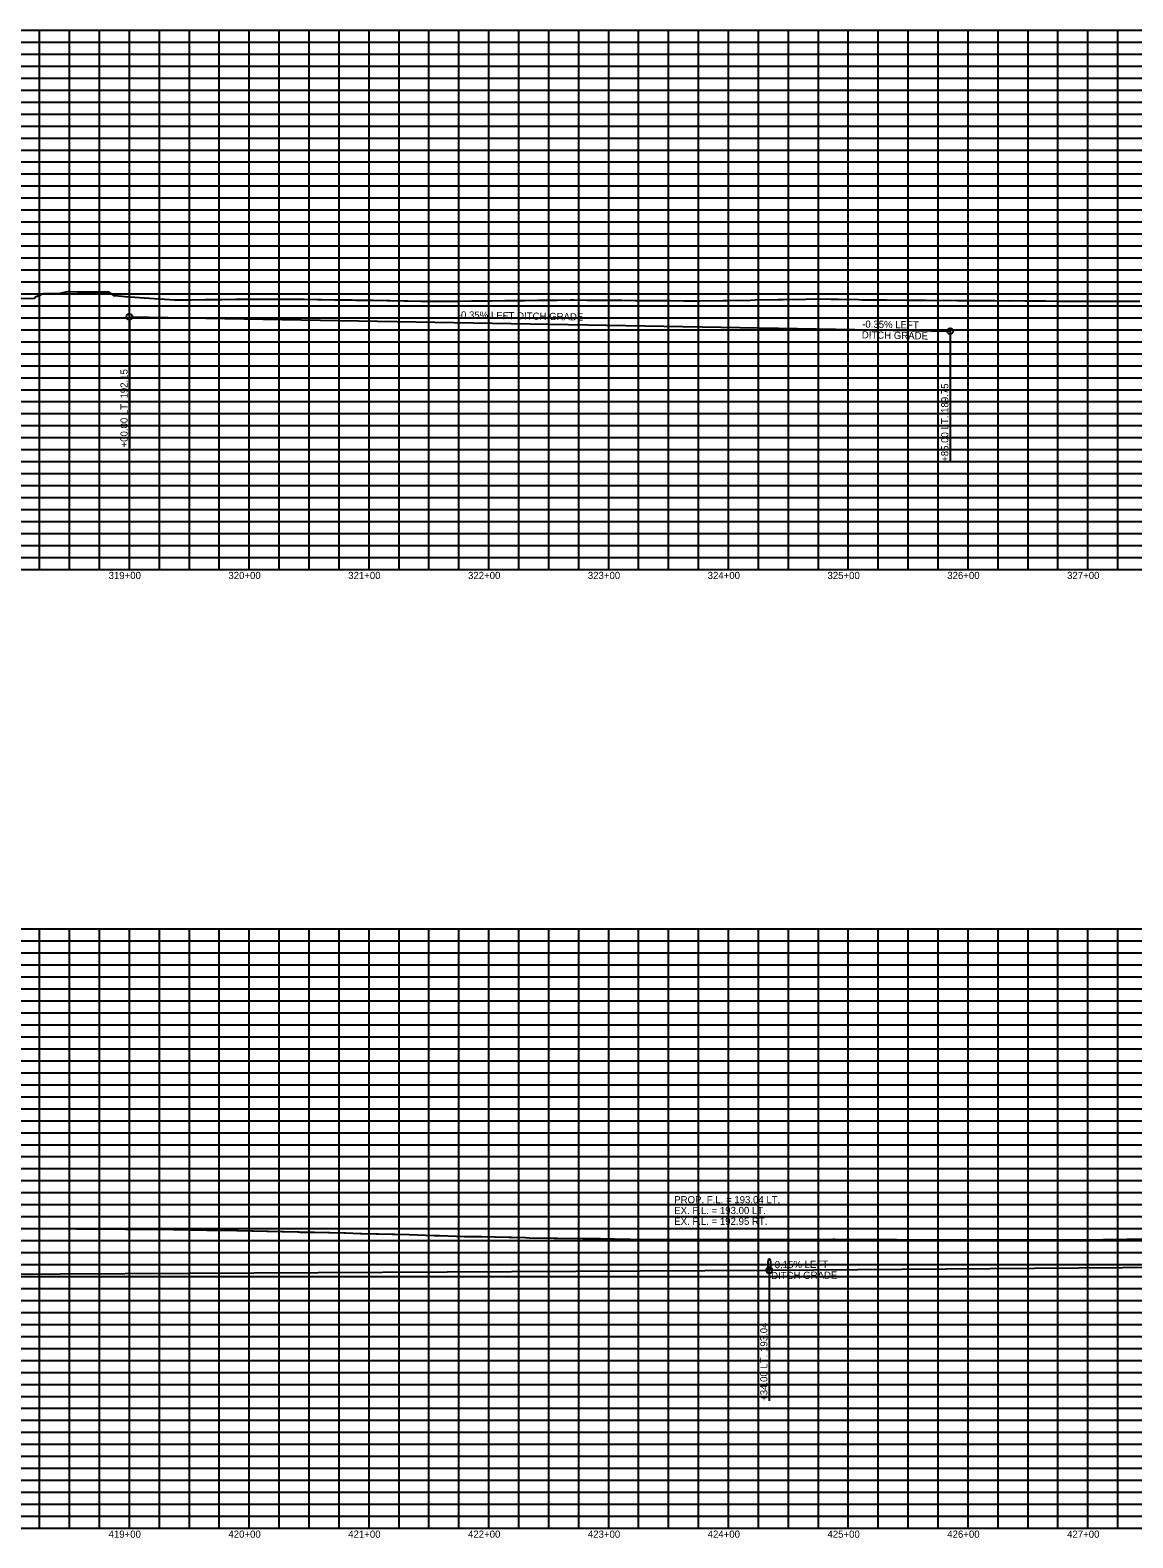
# Model space of a CAD drawing. Extents: x 1399671 to 1408349, y 1930471 to 1933387.
# Drawn here: x 1402141 to 1403062, y 1930471 to 1931729 of the extents above; entities that cross this region are included whole.
import ezdxf

# ---------------------------------------------------------------- set-up
doc = ezdxf.new("R2010")
doc.units = 0
for name, color, linetype in [('R_Drainage', 7, 'Continuous'), ('R_Exist Surface', 7, 'Continuous'), ('R_Grid', 7, 'Continuous'), ('R_Grid Annot', 7, 'Continuous'), ('R_Vert Alg', 7, 'Continuous'), ('R_Vert Alg Annot', 7, 'Continuous')]:
    doc.layers.add(name, color=color, linetype=linetype)

msp = doc.modelspace()

# ---------------------------------------------------------------- linework, layer by layer
at = {"layer": 'R_Drainage'}
msp.add_ellipse((1402758.2, 1930698.6), major_axis=(0, 5), ratio=0.2, dxfattribs=at)
at = {"layer": 'R_Exist Surface'}
for points in [[(1402132, 1931504.6), (1402145.1, 1931504.9), (1402145.9, 1931506.1), (1402152.1, 1931508.8), (1402166.5, 1931509), (1402171.4, 1931510.3), (1402172.5, 1931510.4), (1402180.9, 1931510.2), (1402194, 1931510.3), (1402201.3, 1931510.2), (1402206.6, 1931510.3), (1402210.9, 1931507.1), (1402211.9, 1931507.1), (1402223.8, 1931506.2), (1402224.1, 1931506.2), (1402228.7, 1931505.8), (1402236.5, 1931505.3), (1402236.7, 1931505.2), (1402249, 1931504.4), (1402249.6, 1931504.4), (1402261.6, 1931503.5), (1402262.4, 1931503.5), (1402274.5, 1931503.7), (1402275.5, 1931503.6), (1402287.3, 1931503.8), (1402288.5, 1931503.8), (1402300.1, 1931503.9), (1402301.6, 1931503.9), (1402312.9, 1931504), (1402314.6, 1931504), (1402325.7, 1931504.1), (1402327.7, 1931504.1), (1402329.8, 1931504), (1402340.7, 1931504.1), (1402343.2, 1931504), (1402353.7, 1931504.1), (1402356.5, 1931504), (1402366.7, 1931504.1), (1402370.1, 1931504.1), (1402381.1, 1931503.9), (1402384.5, 1931503.8), (1402395.6, 1931503.7), (1402398.9, 1931503.6), (1402410, 1931503.5), (1402413.2, 1931503.4), (1402424.5, 1931503.3), (1402427.6, 1931503.2), (1402438.9, 1931503), (1402441.9, 1931503), (1402453.4, 1931502.8), (1402456.3, 1931502.8), (1402467.8, 1931502.6), (1402470.6, 1931502.6), (1402482.3, 1931502.4), (1402484.7, 1931502.5), (1402496.1, 1931502.5), (1402498.5, 1931502.6), (1402509.8, 1931502.7), (1402512.3, 1931502.7), (1402523.6, 1931502.8), (1402526.1, 1931502.8), (1402537.4, 1931502.9), (1402540, 1931503), (1402551.1, 1931503.1), (1402553.8, 1931503.1), (1402564.9, 1931503.2), (1402567.5, 1931503.2), (1402578.6, 1931503.3), (1402581.3, 1931503.4), (1402592.4, 1931503.5), (1402595.3, 1931503.5), (1402605.9, 1931503.4), (1402608.7, 1931503.4), (1402619.4, 1931503.3), (1402622.1, 1931503.3), (1402632.9, 1931503.2), (1402635.5, 1931503.2), (1402646.4, 1931503.1), (1402648.9, 1931503.1), (1402659.8, 1931503), (1402662.3, 1931503), (1402673.3, 1931502.9), (1402675.7, 1931502.9), (1402686.8, 1931502.8), (1402689, 1931502.8), (1402700.2, 1931502.7), (1402719.4, 1931503), (1402723.4, 1931503.1), (1402742.6, 1931503.4), (1402746.5, 1931503.5), (1402765.7, 1931503.8), (1402769.7, 1931503.9), (1402788.8, 1931504.2), (1402792.8, 1931504.3), (1402809.7, 1931504.1), (1402812.8, 1931504.1), (1402815.9, 1931504), (1402832.8, 1931503.8), (1402835.9, 1931503.7), (1402852.9, 1931503.6), (1402856, 1931503.5), (1402872.9, 1931503.3), (1402875.3, 1931503.3), (1402887, 1931503.2), (1402889.5, 1931503.2), (1402901.2, 1931503.1), (1402903.7, 1931503.2), (1402915.3, 1931503.1), (1402917.9, 1931503.1), (1402929.5, 1931503), (1402932.2, 1931503), (1402943.6, 1931502.9), (1402946.4, 1931502.9), (1402957.8, 1931502.8), (1402960.6, 1931502.9), (1402971.9, 1931502.8), (1402974.9, 1931502.8), (1402986.1, 1931502.7), (1402988.9, 1931502.7), (1402999.7, 1931502.6), (1403002.4, 1931502.6), (1403013.3, 1931502.6), (1403016, 1931502.6), (1403026.9, 1931502.5), (1403029.5, 1931502.5), (1403040.4, 1931502.5), (1403043.1, 1931502.5), (1403054, 1931502.4), (1403056.7, 1931502.4), (1403067.6, 1931502.4)], [(1402138.2, 1930728.7), (1402152, 1930728.6), (1402165.7, 1930728.6), (1402166.4, 1930728.6), (1402180.1, 1930728.5), (1402180.8, 1930728.5), (1402194.4, 1930728.4), (1402195.2, 1930728.4), (1402207.7, 1930728.3), (1402208.4, 1930728.3), (1402220.9, 1930728.2), (1402221.7, 1930728.2), (1402234.1, 1930728.1), (1402234.9, 1930728.1), (1402247.3, 1930728), (1402248.2, 1930728), (1402260.7, 1930727.9), (1402261.7, 1930727.8), (1402274.2, 1930727.7), (1402275.2, 1930727.6), (1402287.7, 1930727.5), (1402288.8, 1930727.4), (1402301.2, 1930727.2), (1402302.3, 1930727.2), (1402313.8, 1930727), (1402314.9, 1930727), (1402326.4, 1930726.7), (1402327.5, 1930726.7), (1402338.9, 1930726.4), (1402340.1, 1930726.4), (1402351.5, 1930726.2), (1402352.8, 1930726.2), (1402364.5, 1930725.9), (1402365.5, 1930725.8), (1402366.6, 1930725.7), (1402378.6, 1930725.5), (1402390.5, 1930725.2), (1402391.7, 1930725.2), (1402403.6, 1930724.9), (1402404.9, 1930724.9), (1402416.9, 1930724.6), (1402418.2, 1930724.6), (1402430.2, 1930724.2), (1402431.9, 1930724.2), (1402443.9, 1930723.9), (1402445.7, 1930723.9), (1402457.6, 1930723.6), (1402478.4, 1930722.9), (1402480.7, 1930722.9), (1402483.1, 1930722.8), (1402503.9, 1930722.1), (1402515.3, 1930721.9), (1402518, 1930721.9), (1402529.4, 1930721.6), (1402540.8, 1930721.4), (1402543.5, 1930721.3), (1402554.9, 1930721.1), (1402557.7, 1930721), (1402578.8, 1930720.7), (1402581.4, 1930720.7), (1402602.6, 1930720.4), (1402604, 1930720.3), (1402615.9, 1930720.2), (1402617.3, 1930720.2), (1402629.2, 1930720), (1402641, 1930719.8), (1402642.5, 1930719.8), (1402654.3, 1930719.6), (1402655.8, 1930719.6), (1402667.9, 1930719.6), (1402669.4, 1930719.6), (1402681.5, 1930719.6), (1402683, 1930719.5), (1402695.1, 1930719.5), (1402696.6, 1930719.5), (1402708.8, 1930719.5), (1402710.1, 1930719.5), (1402722, 1930719.5), (1402723.4, 1930719.5), (1402735.2, 1930719.5), (1402736.7, 1930719.5), (1402738.4, 1930719.5), (1402750, 1930719.5), (1402751.8, 1930719.5), (1402763.3, 1930719.5), (1402766.7, 1930719.5), (1402787.3, 1930719.6), (1402790.6, 1930719.6), (1402811.3, 1930719.7), (1402813, 1930719.7), (1402824.1, 1930719.6), (1402825.9, 1930719.6), (1402836.9, 1930719.6), (1402838.8, 1930719.5), (1402849.8, 1930719.5), (1402851.7, 1930719.5), (1402862.6, 1930719.4), (1402864.7, 1930719.4), (1402876.5, 1930719.3), (1402878.6, 1930719.3), (1402890.4, 1930719.2), (1402891.2, 1930719.2), (1402892.4, 1930719.2), (1402904.3, 1930719.1), (1402906.3, 1930719.1), (1402918.1, 1930719.1), (1402919.9, 1930719.1), (1402930.7, 1930719.1), (1402932.4, 1930719.1), (1402943.3, 1930719.1), (1402945, 1930719.1), (1402955.9, 1930719.1), (1402957.5, 1930719.1), (1402968.4, 1930719.1), (1402989.7, 1930719.2), (1402992.8, 1930719.2), (1403014.2, 1930719.3), (1403017.2, 1930719.3), (1403019.6, 1930719.3), (1403037, 1930719.5), (1403039.4, 1930719.5), (1403056.9, 1930719.7), (1403058.5, 1930719.7), (1403069.5, 1930719.7)]]:
    msp.add_lwpolyline(points, dxfattribs=at)
at = {"layer": 'R_Grid'}
for p, q in [((1400324.2, 1931728.6), (1408324.2, 1931728.6)), ((1400324.2, 1931728.6), (1408324.2, 1931728.6)), ((1402149.2, 1931278.6), (1402149.2, 1931728.6)), ((1402174.2, 1931278.6), (1402174.2, 1931728.6)), ((1402199.2, 1931278.6), (1402199.2, 1931728.6)), ((1402224.2, 1931278.6), (1402224.2, 1931728.6)), ((1402249.2, 1931278.6), (1402249.2, 1931728.6)), ((1402274.2, 1931278.6), (1402274.2, 1931728.6)), ((1402299.2, 1931278.6), (1402299.2, 1931728.6)), ((1402324.2, 1931278.6), (1402324.2, 1931728.6)), ((1402349.2, 1931278.6), (1402349.2, 1931728.6)), ((1402374.2, 1931278.6), (1402374.2, 1931728.6)), ((1402399.2, 1931278.6), (1402399.2, 1931728.6)), ((1402424.2, 1931278.6), (1402424.2, 1931728.6)), ((1402449.2, 1931278.6), (1402449.2, 1931728.6)), ((1402474.2, 1931278.6), (1402474.2, 1931728.6)), ((1402499.2, 1931278.6), (1402499.2, 1931728.6)), ((1402524.2, 1931278.6), (1402524.2, 1931728.6)), ((1402549.2, 1931278.6), (1402549.2, 1931728.6)), ((1402574.2, 1931278.6), (1402574.2, 1931728.6)), ((1402599.2, 1931278.6), (1402599.2, 1931728.6)), ((1402624.2, 1931278.6), (1402624.2, 1931728.6)), ((1402649.2, 1931278.6), (1402649.2, 1931728.6)), ((1402674.2, 1931278.6), (1402674.2, 1931728.6)), ((1402699.2, 1931278.6), (1402699.2, 1931728.6)), ((1402724.2, 1931278.6), (1402724.2, 1931728.6)), ((1402749.2, 1931278.6), (1402749.2, 1931728.6)), ((1402774.2, 1931278.6), (1402774.2, 1931728.6)), ((1402799.2, 1931278.6), (1402799.2, 1931728.6)), ((1402824.2, 1931278.6), (1402824.2, 1931728.6)), ((1402849.2, 1931278.6), (1402849.2, 1931728.6)), ((1402874.2, 1931278.6), (1402874.2, 1931728.6)), ((1402899.2, 1931278.6), (1402899.2, 1931728.6)), ((1402924.2, 1931278.6), (1402924.2, 1931728.6)), ((1402949.2, 1931278.6), (1402949.2, 1931728.6)), ((1402974.2, 1931278.6), (1402974.2, 1931728.6)), ((1402999.2, 1931278.6), (1402999.2, 1931728.6)), ((1403024.2, 1931278.6), (1403024.2, 1931728.6)), ((1403049.2, 1931278.6), (1403049.2, 1931728.6)), ((1400324.2, 1931718.6), (1408324.2, 1931718.6)), ((1400324.2, 1931708.6), (1408324.2, 1931708.6)), ((1400324.2, 1931698.6), (1408324.2, 1931698.6)), ((1400324.2, 1931688.6), (1408324.2, 1931688.6)), ((1400324.2, 1931678.6), (1408324.2, 1931678.6)), ((1400324.2, 1931668.6), (1408324.2, 1931668.6)), ((1400324.2, 1931658.6), (1408324.2, 1931658.6)), ((1400324.2, 1931648.6), (1408324.2, 1931648.6)), ((1400324.2, 1931638.6), (1408324.2, 1931638.6)), ((1400324.2, 1931628.6), (1408324.2, 1931628.6)), ((1400324.2, 1931618.6), (1408324.2, 1931618.6)), ((1400324.2, 1931608.6), (1408324.2, 1931608.6)), ((1400324.2, 1931598.6), (1408324.2, 1931598.6)), ((1400324.2, 1931588.6), (1408324.2, 1931588.6)), ((1400324.2, 1931578.6), (1408324.2, 1931578.6)), ((1400324.2, 1931568.6), (1408324.2, 1931568.6)), ((1400324.2, 1931558.6), (1408324.2, 1931558.6)), ((1400324.2, 1931548.6), (1408324.2, 1931548.6)), ((1400324.2, 1931538.6), (1408324.2, 1931538.6)), ((1400324.2, 1931528.6), (1408324.2, 1931528.6)), ((1400324.2, 1931518.6), (1408324.2, 1931518.6)), ((1400324.2, 1931508.6), (1408324.2, 1931508.6)), ((1400324.2, 1931498.6), (1408324.2, 1931498.6)), ((1400324.2, 1931488.6), (1408324.2, 1931488.6)), ((1400324.2, 1931478.6), (1408324.2, 1931478.6)), ((1400324.2, 1931468.6), (1408324.2, 1931468.6)), ((1400324.2, 1931458.6), (1408324.2, 1931458.6)), ((1400324.2, 1931448.6), (1408324.2, 1931448.6)), ((1400324.2, 1931438.6), (1408324.2, 1931438.6)), ((1400324.2, 1931428.6), (1408324.2, 1931428.6)), ((1400324.2, 1931418.6), (1408324.2, 1931418.6)), ((1400324.2, 1931408.6), (1408324.2, 1931408.6)), ((1400324.2, 1931398.6), (1408324.2, 1931398.6)), ((1400324.2, 1931388.6), (1408324.2, 1931388.6)), ((1400324.2, 1931378.6), (1408324.2, 1931378.6)), ((1400324.2, 1931368.6), (1408324.2, 1931368.6)), ((1400324.2, 1931358.6), (1408324.2, 1931358.6)), ((1400324.2, 1931348.6), (1408324.2, 1931348.6)), ((1400324.2, 1931338.6), (1408324.2, 1931338.6)), ((1400324.2, 1931328.6), (1408324.2, 1931328.6)), ((1400324.2, 1931318.6), (1408324.2, 1931318.6)), ((1400324.2, 1931308.6), (1408324.2, 1931308.6)), ((1400324.2, 1931298.6), (1408324.2, 1931298.6)), ((1400324.2, 1931288.6), (1408324.2, 1931288.6)), ((1400324.2, 1931278.6), (1408324.2, 1931278.6)), ((1400324.2, 1930978.6), (1407124.2, 1930978.6)), ((1400324.2, 1930978.6), (1407124.2, 1930978.6)), ((1402149.2, 1930478.6), (1402149.2, 1930978.6)), ((1402174.2, 1930478.6), (1402174.2, 1930978.6)), ((1402199.2, 1930478.6), (1402199.2, 1930978.6)), ((1402224.2, 1930478.6), (1402224.2, 1930978.6)), ((1402249.2, 1930478.6), (1402249.2, 1930978.6)), ((1402274.2, 1930478.6), (1402274.2, 1930978.6)), ((1402299.2, 1930478.6), (1402299.2, 1930978.6)), ((1402324.2, 1930478.6), (1402324.2, 1930978.6)), ((1402349.2, 1930478.6), (1402349.2, 1930978.6)), ((1402374.2, 1930478.6), (1402374.2, 1930978.6)), ((1402399.2, 1930478.6), (1402399.2, 1930978.6)), ((1402424.2, 1930478.6), (1402424.2, 1930978.6)), ((1402449.2, 1930478.6), (1402449.2, 1930978.6)), ((1402474.2, 1930478.6), (1402474.2, 1930978.6)), ((1402499.2, 1930478.6), (1402499.2, 1930978.6)), ((1402524.2, 1930478.6), (1402524.2, 1930978.6)), ((1402549.2, 1930478.6), (1402549.2, 1930978.6)), ((1402574.2, 1930478.6), (1402574.2, 1930978.6)), ((1402599.2, 1930478.6), (1402599.2, 1930978.6)), ((1402624.2, 1930478.6), (1402624.2, 1930978.6)), ((1402649.2, 1930478.6), (1402649.2, 1930978.6)), ((1402674.2, 1930478.6), (1402674.2, 1930978.6)), ((1402699.2, 1930478.6), (1402699.2, 1930978.6)), ((1402724.2, 1930478.6), (1402724.2, 1930978.6)), ((1402749.2, 1930478.6), (1402749.2, 1930978.6)), ((1402774.2, 1930478.6), (1402774.2, 1930978.6)), ((1402799.2, 1930478.6), (1402799.2, 1930978.6)), ((1402824.2, 1930478.6), (1402824.2, 1930978.6)), ((1402849.2, 1930478.6), (1402849.2, 1930978.6)), ((1402874.2, 1930478.6), (1402874.2, 1930978.6)), ((1402899.2, 1930478.6), (1402899.2, 1930978.6)), ((1402924.2, 1930478.6), (1402924.2, 1930978.6)), ((1402949.2, 1930478.6), (1402949.2, 1930978.6)), ((1402974.2, 1930478.6), (1402974.2, 1930978.6)), ((1402999.2, 1930478.6), (1402999.2, 1930978.6)), ((1403024.2, 1930478.6), (1403024.2, 1930978.6)), ((1403049.2, 1930478.6), (1403049.2, 1930978.6)), ((1400324.2, 1930968.6), (1407124.2, 1930968.6)), ((1400324.2, 1930958.6), (1407124.2, 1930958.6)), ((1400324.2, 1930948.6), (1407124.2, 1930948.6)), ((1400324.2, 1930938.6), (1407124.2, 1930938.6)), ((1400324.2, 1930928.6), (1407124.2, 1930928.6)), ((1400324.2, 1930918.6), (1407124.2, 1930918.6)), ((1400324.2, 1930908.6), (1407124.2, 1930908.6)), ((1400324.2, 1930898.6), (1407124.2, 1930898.6)), ((1400324.2, 1930888.6), (1407124.2, 1930888.6)), ((1400324.2, 1930878.6), (1407124.2, 1930878.6)), ((1400324.2, 1930868.6), (1407124.2, 1930868.6)), ((1400324.2, 1930858.6), (1407124.2, 1930858.6)), ((1400324.2, 1930848.6), (1407124.2, 1930848.6)), ((1400324.2, 1930838.6), (1407124.2, 1930838.6)), ((1400324.2, 1930828.6), (1407124.2, 1930828.6)), ((1400324.2, 1930818.6), (1407124.2, 1930818.6)), ((1400324.2, 1930808.6), (1407124.2, 1930808.6)), ((1400324.2, 1930798.6), (1407124.2, 1930798.6)), ((1400324.2, 1930788.6), (1407124.2, 1930788.6)), ((1400324.2, 1930778.6), (1407124.2, 1930778.6)), ((1400324.2, 1930768.6), (1407124.2, 1930768.6)), ((1400324.2, 1930758.6), (1407124.2, 1930758.6)), ((1400324.2, 1930748.6), (1407124.2, 1930748.6)), ((1400324.2, 1930738.6), (1407124.2, 1930738.6)), ((1400324.2, 1930728.6), (1407124.2, 1930728.6)), ((1400324.2, 1930718.6), (1407124.2, 1930718.6)), ((1400324.2, 1930708.6), (1407124.2, 1930708.6)), ((1400324.2, 1930698.6), (1407124.2, 1930698.6)), ((1400324.2, 1930688.6), (1407124.2, 1930688.6)), ((1400324.2, 1930678.6), (1407124.2, 1930678.6)), ((1400324.2, 1930668.6), (1407124.2, 1930668.6)), ((1400324.2, 1930658.6), (1407124.2, 1930658.6)), ((1400324.2, 1930648.6), (1407124.2, 1930648.6)), ((1400324.2, 1930638.6), (1407124.2, 1930638.6)), ((1400324.2, 1930628.6), (1407124.2, 1930628.6)), ((1400324.2, 1930618.6), (1407124.2, 1930618.6)), ((1400324.2, 1930608.6), (1407124.2, 1930608.6)), ((1400324.2, 1930598.6), (1407124.2, 1930598.6)), ((1400324.2, 1930588.6), (1407124.2, 1930588.6)), ((1400324.2, 1930578.6), (1407124.2, 1930578.6)), ((1400324.2, 1930568.6), (1407124.2, 1930568.6)), ((1400324.2, 1930558.6), (1407124.2, 1930558.6)), ((1400324.2, 1930548.6), (1407124.2, 1930548.6)), ((1400324.2, 1930538.6), (1407124.2, 1930538.6)), ((1400324.2, 1930528.6), (1407124.2, 1930528.6)), ((1400324.2, 1930518.6), (1407124.2, 1930518.6)), ((1400324.2, 1930508.6), (1407124.2, 1930508.6)), ((1400324.2, 1930498.6), (1407124.2, 1930498.6)), ((1400324.2, 1930488.6), (1407124.2, 1930488.6)), ((1400324.2, 1930478.6), (1407124.2, 1930478.6))]:
    msp.add_line(p, q, dxfattribs=at)
at = {"layer": 'R_Vert Alg'}
for p, q in [((1402224.2, 1931489.4), (1402909.2, 1931477.4)), ((1402758.2, 1930693.8), (1404524.2, 1930707.1)), ((1400924.2, 1930684.7), (1402758.2, 1930693.8))]:
    msp.add_line(p, q, dxfattribs=at)
at = {"layer": 'R_Vert Alg Annot'}
for p, q in [((1402224.2, 1931489.4), (1402224.2, 1931464.4)), ((1402909.2, 1931477.4), (1402909.2, 1931452.4)), ((1402224.2, 1931464.4), (1402224.2, 1931380.4)), ((1402909.2, 1931452.4), (1402909.2, 1931368.4)), ((1402758.2, 1930693.8), (1402758.2, 1930668.8)), ((1402758.2, 1930668.8), (1402758.2, 1930584.8))]:
    msp.add_line(p, q, dxfattribs=at)
for centre in [(1402224.2, 1931489.4), (1402909.2, 1931477.4), (1402758.2, 1930693.8)]:
    msp.add_circle(centre, 2.5, dxfattribs=at)

# ---------------------------------------------------------------- texts
at = {"layer": 'R_Grid Annot'}
for s, p in [('319+00', (1402206.8, 1931270.6)), ('320+00', (1402306.8, 1931270.6)), ('321+00', (1402406.8, 1931270.6)), ('322+00', (1402506.8, 1931270.6)), ('323+00', (1402606.8, 1931270.6)), ('324+00', (1402706.8, 1931270.6)), ('325+00', (1402806.8, 1931270.6)), ('326+00', (1402906.8, 1931270.6)), ('327+00', (1403006.8, 1931270.6)), ('419+00', (1402206.8, 1930470.6)), ('420+00', (1402306.8, 1930470.6)), ('421+00', (1402406.8, 1930470.6)), ('422+00', (1402506.8, 1930470.6)), ('423+00', (1402606.8, 1930470.6)), ('424+00', (1402706.8, 1930470.6)), ('425+00', (1402806.8, 1930470.6)), ('426+00', (1402906.8, 1930470.6)), ('427+00', (1403006.8, 1930470.6))]:
    msp.add_text(s, height=6, dxfattribs=at).set_placement(p)
at = {"layer": 'R_Vert Alg Annot'}
for s, rotation, p in [('-0.35% LEFT DITCH GRADE', 358.9964, (1402498.2, 1931488.1)), ('DITCH GRADE', 358.9964, (1402835.4, 1931471.4)), ('-0.35% LEFT', 358.9964, (1402835.7, 1931480.4)), ('+00.00 LT. 192.15', 90, (1402222.7, 1931380.4)), ('+85.00 LT. 189.75', 90, (1402907.7, 1931368.4)), ('0.15% LEFT', 0.4299, (1402762.8, 1930695.5)), ('DITCH GRADE', 0.4299, (1402759.8, 1930686.4)), ('+34.00 LT. 193.04', 90, (1402756.7, 1930584.8))]:
    msp.add_text(s, height=6, rotation=rotation, dxfattribs=at).set_placement(p)
for s, p in [('PROP. F.L. = 193.04 LT.', (1402678.9, 1930749.7)), ('EX. F.L. = 193.00 LT.', (1402678.9, 1930740.7)), ('EX. F.L. = 192.95 RT.', (1402678.9, 1930731.7))]:
    msp.add_text(s, height=6, dxfattribs=at).set_placement(p)

doc.saveas('drawing.dxf')
